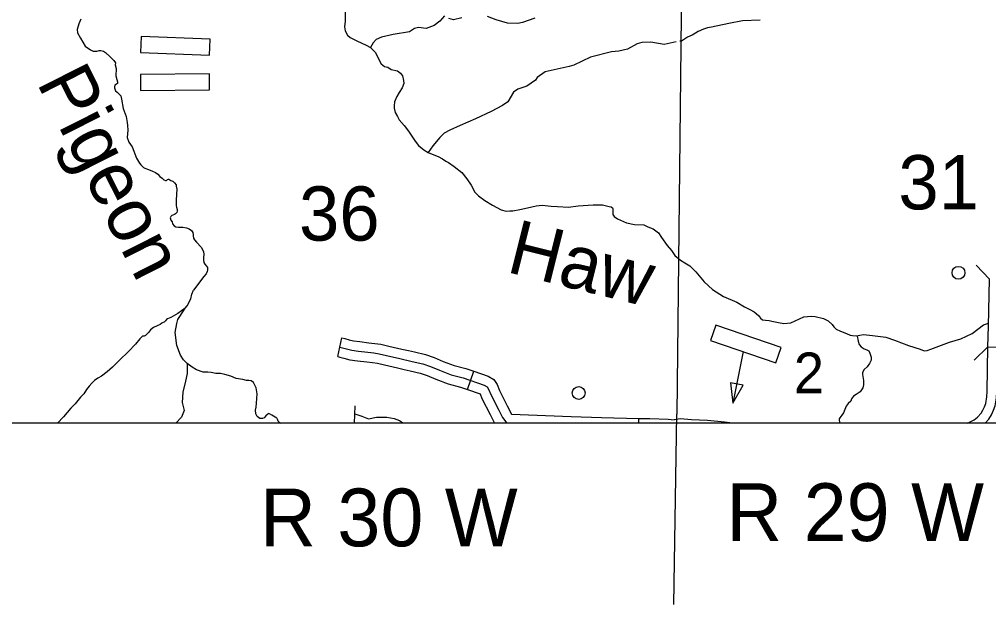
# Model space of a CAD drawing. Extents: x 1382482 to 1385815, y 1168351 to 1170484.
# Drawn here: x 1383865.9 to 1384167.8, y 1168645.8 to 1168828.2 of the extents above; entities that cross this region are included whole.
import ezdxf

# ---------------------------------------------------------------- set-up
doc = ezdxf.new("R2010")
doc.units = 0
for name, color, linetype in [('35', 7, 'Continuous'), ('38', 7, 'Continuous'), ('4', 7, 'Continuous'), ('45', 7, 'Continuous'), ('5', 7, 'Continuous'), ('57', 7, 'Continuous'), ('Default', 7, 'Continuous'), ('R_Dimension', 7, 'Continuous'), ('R_No Plot', 7, 'Continuous')]:
    doc.layers.add(name, color=color, linetype=linetype)

msp = doc.modelspace()

# ---------------------------------------------------------------- linework, layer by layer
at = {"layer": '35'}
for points in [[(1383967.32, 1168830.76), (1383967.32, 1168827.61), (1383967.16, 1168825.81), (1383967.32, 1168824.54), (1383968.06, 1168823.23), (1383968.87, 1168822.46), (1383971.04, 1168821.48), (1383973.9, 1168820.13), (1383975.23, 1168819.36), (1383976.85, 1168817.84), (1383977.87, 1168815.63), (1383978.61, 1168814.32), (1383979.63, 1168813.51), (1383980.65, 1168813.3), (1383981.74, 1168812.59), (1383983.62, 1168812.09), (1383984.6, 1168811.36), (1383985.26, 1168810.58), (1383985.58, 1168809.15), (1383985.62, 1168808.13), (1383985.13, 1168806.82), (1383984.23, 1168805.39), (1383983.42, 1168804.08), (1383982.76, 1168802.48), (1383982.6, 1168801.17), (1383982.6, 1168800.48), (1383982.92, 1168799.17), (1383983.66, 1168797.86), (1383984.19, 1168796.84), (1383985.71, 1168795.08), (1383987.06, 1168793.36), (1383989.22, 1168790.26), (1383990.2, 1168788.91), (1383991.88, 1168787.48), (1383993.23, 1168786.71), (1383994.42, 1168786.13), (1383996.34, 1168785.4), (1383997.69, 1168784.7), (1383998.75, 1168784.01), (1383999.53, 1168783.56), (1384001.29, 1168782.29), (1384003.74, 1168780.45), (1384005.25, 1168778.52), (1384006.64, 1168776.48), (1384007.75, 1168774.31), (1384008.85, 1168773.17), (1384010.9, 1168771.77), (1384013.23, 1168770.26), (1384016.01, 1168768.79), (1384017.49, 1168768.4)], [(1383998.29, 1168829.21), (1383996.89, 1168827.55), (1383995.1, 1168826.21), (1383992.59, 1168825.27), (1383990.2, 1168825.64), (1383989.01, 1168825.35), (1383987.36, 1168824.31), (1383982.29, 1168823.43), (1383978.7, 1168822.6), (1383977.07, 1168821.86), (1383976.04, 1168820.81), (1383975.23, 1168819.36)], [(1384026.45, 1168828.51), (1384022.58, 1168827.16), (1384021.15, 1168826.86), (1384017.91, 1168827), (1384014.38, 1168828.05), (1384011.74, 1168829.07)], [(1383885, 1168828.24), (1383884.39, 1168826.72), (1383883.86, 1168825.04), (1383883.98, 1168823.94), (1383884.92, 1168822.26), (1383886.31, 1168819.81), (1383888.03, 1168818.66), (1383888.89, 1168818.25), (1383889.3, 1168818.21), (1383889.7, 1168818.25), (1383889.95, 1168818.29), (1383890.4, 1168818.33), (1383890.69, 1168818.41), (1383891.26, 1168818.41), (1383892.03, 1168818.25), (1383892.69, 1168817.8), (1383894.12, 1168816.49), (1383895.27, 1168815.39), (1383895.8, 1168814.65), (1383895.67, 1168814.04), (1383896.04, 1168812.81), (1383895.92, 1168810.52), (1383896.21, 1168809.42), (1383896.41, 1168808.68), (1383896.41, 1168808.23), (1383896.12, 1168808.02), (1383895.63, 1168807.66), (1383895.47, 1168807.17), (1383895.51, 1168806.8), (1383895.84, 1168805.9), (1383896.33, 1168805.49), (1383896.66, 1168805.2), (1383897.11, 1168804.63), (1383897.43, 1168804.3), (1383897.68, 1168803.29), (1383898.17, 1168800.35), (1383899.15, 1168797.89), (1383899.48, 1168796.01), (1383899.59, 1168795.11), (1383899.63, 1168793.6), (1383899.4, 1168791.35), (1383899.97, 1168789.88), (1383900.95, 1168788.49), (1383902.35, 1168784.9)], [(1384003.74, 1168828.66), (1384001.1, 1168827.97), (1383999.68, 1168828.46)], [(1384096.7, 1168827.92), (1384091.16, 1168827.67), (1384086.87, 1168826.86), (1384081.53, 1168825.71), (1384080.22, 1168825.52), (1384078.97, 1168825.15), (1384077.38, 1168824.34), (1384076.52, 1168823.85), (1384075.49, 1168823.26), (1384073.99, 1168822.64), (1384072.1, 1168821.42), (1384071.66, 1168821.34)], [(1384070.52, 1168821.12), (1384069.54, 1168820.93), (1384066.71, 1168820.31), (1384062.55, 1168821.03), (1384059.83, 1168820.93), (1384058.28, 1168820.52), (1384055.3, 1168818.89), (1384052.66, 1168818.23), (1384050.35, 1168818.05), (1384043.84, 1168816.38), (1384038.65, 1168813.91), (1384037.19, 1168813.45), (1384029.69, 1168811.84), (1384027.2, 1168810.02), (1384026.62, 1168809.2), (1384023.92, 1168807.38), (1384021.15, 1168806.43), (1384019.8, 1168805.46), (1384018.03, 1168802.42), (1384016.38, 1168801.33), (1384012.87, 1168799.5), (1384007.93, 1168797.14), (1384003.15, 1168795.06), (1383999.99, 1168793.67), (1383998.25, 1168792.7), (1383996.9, 1168791.38), (1383994.66, 1168788.81), (1383993.27, 1168786.65)], [(1383902.35, 1168784.9), (1383903.33, 1168783.4), (1383903.67, 1168782.87), (1383904.08, 1168782.42), (1383904.51, 1168782.03), (1383904.96, 1168781.79), (1383906.05, 1168781.38), (1383907.38, 1168780.85), (1383908.23, 1168780.48), (1383908.97, 1168779.93), (1383909.62, 1168779.25), (1383910.32, 1168778.66), (1383910.87, 1168778.17), (1383911.42, 1168777.92), (1383911.71, 1168777.96), (1383911.85, 1168778.05), (1383911.96, 1168778.25), (1383912.3, 1168778.35), (1383912.47, 1168778.33), (1383913, 1168778.01), (1383913.67, 1168777.7), (1383914.23, 1168777.19), (1383914.7, 1168776.61), (1383914.76, 1168776.23), (1383914.9, 1168775.24), (1383914.78, 1168773.69), (1383914.76, 1168771.75), (1383914.68, 1168770.48), (1383914.76, 1168770.03), (1383914.84, 1168769.6), (1383915, 1168768.92), (1383915.06, 1168768.37), (1383914.92, 1168767.98), (1383914.53, 1168767.57), (1383914.16, 1168767.35), (1383913.67, 1168767.16), (1383913.33, 1168767.04), (1383913.06, 1168766.73), (1383912.88, 1168766.32), (1383913.02, 1168765.64), (1383913.43, 1168765.03), (1383913.55, 1168764.45), (1383914.08, 1168763.82), (1383914.61, 1168763.49), (1383915.45, 1168763.47), (1383916.07, 1168763.47), (1383916.8, 1168763.45), (1383917.93, 1168763.21), (1383918.78, 1168762.92), (1383919.44, 1168762.35), (1383919.95, 1168761.71), (1383920.01, 1168761.06), (1383920.01, 1168760.73), (1383920.13, 1168760.02), (1383920.42, 1168759.46), (1383921.05, 1168758.75), (1383922.51, 1168757.16), (1383923.26, 1168755.81), (1383923.32, 1168754.91), (1383923.26, 1168753.99), (1383923.24, 1168753.17), (1383923.37, 1168752.39), (1383923.59, 1168751.94), (1383924.14, 1168751.29), (1383924.45, 1168750.86), (1383924.49, 1168750.08), (1383924.39, 1168749.57), (1383924.1, 1168748.84), (1383923.3, 1168748.04), (1383920.1, 1168743.84)], [(1384017.49, 1168768.4), (1384018.64, 1168768.46), (1384019.61, 1168768.52), (1384021.78, 1168768.89), (1384024.2, 1168769.43), (1384026.91, 1168770.04), (1384028.72, 1168770.28), (1384031.56, 1168769.97), (1384033.56, 1168769.91), (1384036.94, 1168769.61), (1384039.96, 1168770.04), (1384041.47, 1168770.22), (1384044.67, 1168770.4), (1384047.51, 1168770.34), (1384049.56, 1168769.91), (1384050.23, 1168769.73), (1384050.65, 1168769.43), (1384050.77, 1168769.25), (1384050.71, 1168768.89), (1384050.71, 1168768.22), (1384050.77, 1168767.38), (1384051.19, 1168766.71), (1384052.22, 1168766.05), (1384055.06, 1168764.72), (1384057.53, 1168764.24), (1384060.43, 1168764.17), (1384061.64, 1168763.57), (1384063.33, 1168762.91), (1384065.02, 1168761.7), (1384065.87, 1168760.19), (1384067.7, 1168757.71), (1384069.03, 1168756.14), (1384070.1, 1168754.63), (1384071.79, 1168753.18), (1384073.18, 1168752.33), (1384074.78, 1168751.34), (1384076.66, 1168749.52), (1384079.19, 1168746.44), (1384081.79, 1168744.03), (1384085.23, 1168741.79), (1384089.4, 1168740.1), (1384091.81, 1168738.59), (1384093.45, 1168737.8), (1384094.77, 1168737.08), (1384096.16, 1168735.93), (1384096.71, 1168735.02), (1384097.43, 1168734.54), (1384098.34, 1168734.42), (1384099.42, 1168734.36), (1384100.33, 1168734.12), (1384102.38, 1168733.76), (1384103.98, 1168733.39), (1384106.21, 1168733.63), (1384107.6, 1168734.24), (1384110.26, 1168735.45), (1384112.55, 1168735.69), (1384113.77, 1168735.59), (1384116.42, 1168734.98), (1384117.81, 1168734.24), (1384119.08, 1168733.09), (1384119.56, 1168732.37), (1384120.29, 1168731.64), (1384121.67, 1168731.04), (1384123.55, 1168730.25), (1384124.69, 1168729.77), (1384125.43, 1168729.67), (1384126.57, 1168729.53), (1384128.86, 1168729.95), (1384131.7, 1168729.71), (1384134.12, 1168729.35), (1384135.81, 1168729.1)], [(1383919.72, 1168719.85), (1383918.14, 1168720.95), (1383916.96, 1168722.05), (1383916.02, 1168723.59), (1383914.95, 1168726.58), (1383914.42, 1168730.59), (1383914.87, 1168733.41), (1383915.24, 1168734.68), (1383915.9, 1168735.58), (1383917.55, 1168738.22), (1383918.14, 1168738.93), (1383919.29, 1168741.14), (1383919.58, 1168742.53), (1383920.1, 1168743.84)], [(1383917.55, 1168738.22), (1383915.22, 1168736.55), (1383913.06, 1168735.31), (1383911.99, 1168734.84), (1383911.74, 1168734.66), (1383911.42, 1168734.22), (1383910.95, 1168733.82), (1383910.7, 1168733.73), (1383910.21, 1168733.53), (1383909.7, 1168733.08), (1383908.82, 1168732.71), (1383907.68, 1168732.12), (1383906.73, 1168731.45), (1383906.04, 1168730.63), (1383905.12, 1168729.62), (1383904.69, 1168729.42), (1383904.26, 1168729.42), (1383903.93, 1168729.11), (1383903.44, 1168728.66), (1383901.99, 1168726.99), (1383899.82, 1168724.7), (1383897.06, 1168721.97), (1383894.86, 1168719.81), (1383893.22, 1168718.35), (1383891.44, 1168717), (1383890.34, 1168716.35), (1383889.29, 1168715.68), (1383888.41, 1168714.86), (1383887.62, 1168713.85), (1383886.78, 1168712.85), (1383885.92, 1168711.54), (1383884.92, 1168710.48), (1383883.2, 1168708.43), (1383881.93, 1168706.98), (1383879.56, 1168704.36), (1383877.74, 1168702.36)], [(1384135.81, 1168729.1), (1384138.49, 1168728.22), (1384142.84, 1168726.58), (1384146.53, 1168725.38), (1384147.74, 1168724.89), (1384148.64, 1168724.95), (1384149.79, 1168725.44), (1384152.27, 1168726.34), (1384155.59, 1168727.55), (1384159.21, 1168728.64), (1384162.71, 1168730.33), (1384166.22, 1168732.99), (1384167.78, 1168733.53)], [(1384126.9, 1168729.59), (1384127.2, 1168727.93), (1384127.54, 1168726.83), (1384128.09, 1168726.15), (1384129.02, 1168725.52), (1384129.87, 1168725.22), (1384130.5, 1168724.89), (1384130.84, 1168724.13), (1384131.22, 1168722.9), (1384131.22, 1168721.97), (1384130.67, 1168720.91), (1384130.03, 1168719.9), (1384129.02, 1168719.1), (1384128.51, 1168718.17), (1384128.56, 1168717.49), (1384128.89, 1168715.63), (1384128.81, 1168714.28), (1384128.68, 1168713.35), (1384127.79, 1168712.12), (1384126.57, 1168711.32), (1384125.77, 1168710.77), (1384125.13, 1168709.89), (1384124.88, 1168709.16), (1384124.09, 1168708.51), (1384123.46, 1168707.62), (1384122.6, 1168705.57), (1384122.13, 1168704.86), (1384121.49, 1168703.98), (1384121.31, 1168703.73), (1384121.38, 1168702.36)], [(1383918.14, 1168720.95), (1383918.14, 1168717.88), (1383917.61, 1168715.46), (1383916.79, 1168712.02), (1383916.63, 1168708.75), (1383917.2, 1168706.31), (1383916.38, 1168704.19), (1383914.63, 1168702.36)], [(1383946.11, 1168703.91), (1383944.5, 1168704.88), (1383943.81, 1168705.29), (1383943.46, 1168705.33), (1383943.27, 1168705.21), (1383942.62, 1168704.59), (1383942.17, 1168704.06), (1383941.6, 1168703.77), (1383940.74, 1168703.81), (1383939.92, 1168704.39), (1383939.57, 1168705.23), (1383939.47, 1168706.43), (1383939.61, 1168707.33), (1383939.76, 1168708.56), (1383939.96, 1168711.46), (1383939.68, 1168713.39), (1383938.82, 1168715.02), (1383938.04, 1168715.51), (1383937.39, 1168715.64), (1383936.61, 1168715.68), (1383935.45, 1168715.95), (1383933.37, 1168716.32), (1383931.72, 1168716.96), (1383929.9, 1168717.48), (1383928.47, 1168717.81), (1383927.08, 1168717.85), (1383925.65, 1168718.09), (1383924.61, 1168718.29), (1383923.13, 1168718.29), (1383921.09, 1168718.93), (1383919.72, 1168719.85), (1383919.71, 1168719.85)], [(1383970.38, 1168707.79), (1383970.18, 1168702.36)], [(1383970.29, 1168705.29), (1383970.38, 1168705.27), (1383972.52, 1168704.51), (1383974.62, 1168703.74), (1383977.14, 1168704.18), (1383979.02, 1168704.24), (1383980.34, 1168704.24), (1383982.65, 1168703.79), (1383984.29, 1168703.21), (1383985.19, 1168702.53), (1383985.28, 1168702.36)], [(1383946.11, 1168703.91), (1383946.2, 1168703.75), (1383946.38, 1168703.12), (1383946.85, 1168702.68), (1383947.19, 1168702.36)]]:
    msp.add_lwpolyline(points, dxfattribs=at)
at = {"layer": '38'}
for points in [[(1384168.07, 1168747.22), (1384163.92, 1168751.55)], [(1384163.3, 1168721.94), (1384167.63, 1168726.1)]]:
    msp.add_lwpolyline(points, dxfattribs=at)
at = {"layer": '4'}
msp.add_lwpolyline([(1384072.84, 1168894.38), (1384072.4, 1168859.16), (1384072.39, 1168858.03), (1384070.68, 1168705.11)], dxfattribs=at)
at = {"layer": '45'}
for p, q in [((1383965.04, 1168723.11), (1383966.29, 1168728.98)), ((1384005.48, 1168712.84), (1384007.43, 1168718.51)), ((1384058.8, 1168702.36), (1384058.84, 1168703.85))]:
    msp.add_line(p, q, dxfattribs=at)
for points in [[(1383965.67, 1168726.05), (1383966.51, 1168725.87), (1383967.78, 1168725.47), (1383969.41, 1168725.05), (1383971.55, 1168724.78), (1383974.42, 1168724.45), (1383976.27, 1168724.23), (1383977.96, 1168723.99), (1383980.25, 1168723.45), (1383984.36, 1168722.51), (1383988.25, 1168721.61), (1383991.55, 1168720.82), (1383993.99, 1168720), (1383996.71, 1168718.83), (1384000.39, 1168717.44), (1384004.14, 1168716.47), (1384010.66, 1168714.24), (1384011.57, 1168713.69), (1384012.05, 1168712.97), (1384012.71, 1168711.27), (1384015.19, 1168706.44), (1384016.34, 1168704.15), (1384017.43, 1168702.79), (1384017.72, 1168702.36)], [(1383966.29, 1168728.98), (1383967.27, 1168728.77), (1383968.6, 1168728.36), (1383969.98, 1168728), (1383971.92, 1168727.76), (1383974.77, 1168727.43), (1383976.65, 1168727.21), (1383978.52, 1168726.94), (1383980.93, 1168726.37), (1383985.03, 1168725.44), (1383987.05, 1168724.97)], [(1383965.04, 1168723.11), (1383965.75, 1168722.96), (1383966.96, 1168722.59), (1383968.84, 1168722.1), (1383971.19, 1168721.8), (1383974.08, 1168721.47), (1383975.88, 1168721.26), (1383977.4, 1168721.04), (1383979.57, 1168720.53), (1383983.69, 1168719.59), (1383985.69, 1168719.12)], [(1383987.05, 1168724.97), (1383988.94, 1168724.53), (1383992.37, 1168723.71), (1383995.06, 1168722.81), (1383997.84, 1168721.61), (1384001.3, 1168720.3), (1384005, 1168719.35), (1384007.43, 1168718.51)], [(1383985.69, 1168719.12), (1383987.57, 1168718.69), (1383990.72, 1168717.93), (1383992.92, 1168717.2), (1383995.58, 1168716.05), (1383999.49, 1168714.57), (1384003.28, 1168713.59), (1384005.48, 1168712.84)], [(1384007.43, 1168718.51), (1384011.93, 1168716.97), (1384013.69, 1168715.92), (1384014.73, 1168714.36), (1384015.45, 1168712.51), (1384017.87, 1168707.8), (1384019.21, 1168705.12)], [(1384005.48, 1168712.84), (1384009.39, 1168711.5), (1384009.41, 1168711.49), (1384009.98, 1168710.04), (1384012.51, 1168705.09), (1384013.87, 1168702.36)], [(1384019.21, 1168705.12), (1384037.75, 1168704.48)], [(1384037.75, 1168704.48), (1384047.27, 1168704.15), (1384058.84, 1168703.85)], [(1384058.84, 1168703.85), (1384062.27, 1168703.76), (1384068, 1168703.65), (1384069.88, 1168703.37)], [(1384087.21, 1168702.44), (1384085.58, 1168702.66), (1384080.2, 1168703.15), (1384075.23, 1168703.39), (1384071.7, 1168703.68), (1384069.88, 1168703.37)], [(1384087.8, 1168702.36), (1384087.21, 1168702.44)]]:
    msp.add_lwpolyline(points, dxfattribs=at)
at = {"layer": '57'}
for p, q in [((1383903.8, 1168822.83), (1383903.61, 1168817.83)), ((1383925.28, 1168822.01), (1383903.8, 1168822.83)), ((1383925.09, 1168817.01), (1383925.28, 1168822.01)), ((1383903.61, 1168817.83), (1383925.09, 1168817.01)), ((1383925.09, 1168811.17), (1383903.59, 1168810.99)), ((1383903.59, 1168810.99), (1383903.63, 1168805.99)), ((1383925.13, 1168806.17), (1383925.09, 1168811.17)), ((1383903.63, 1168805.99), (1383925.13, 1168806.17)), ((1384082.81, 1168732.88), (1384081.19, 1168728.15)), ((1384103.15, 1168725.92), (1384082.81, 1168732.88)), ((1384081.19, 1168728.15), (1384101.53, 1168721.19)), ((1384101.53, 1168721.19), (1384103.15, 1168725.92))]:
    msp.add_line(p, q, dxfattribs=at)
msp.add_lwpolyline([(1384091.36, 1168724.67), (1384088.18, 1168708.56)], dxfattribs=at)
msp.add_lwpolyline([(1384091.36, 1168714.17), (1384087.36, 1168714.96), (1384088.18, 1168708.56)], close=True, dxfattribs=at)
at = {"layer": 'Default'}
msp.add_line((1384167.63, 1168726.1), (1384173.63, 1168725.97), dxfattribs=at)
for points in [[(1384166.76, 1168702.36), (1384167.86, 1168703.6), (1384168.73, 1168704.94), (1384169.35, 1168706.36), (1384169.87, 1168707.74), (1384170.24, 1168710.26), (1384170.35, 1168712.16), (1384170.76, 1168732.56), (1384172.28, 1168804.42), (1384172.97, 1168852.13), (1384172.97, 1168888.73), (1384172.69, 1168911.31), (1384172.24, 1168922.6)], [(1384167.63, 1168726.1), (1384167.76, 1168732.62), (1384168.07, 1168747.21)], [(1384166.07, 1168706.36), (1384166.57, 1168707.49), (1384166.95, 1168708.5), (1384167.26, 1168710.56), (1384167.35, 1168712.27), (1384167.63, 1168726.1)], [(1384161.28, 1168702.36), (1384162.07, 1168702.73), (1384163.37, 1168703.43), (1384164.37, 1168704.19), (1384165.47, 1168705.42), (1384166.07, 1168706.36), (1384166.07, 1168706.36)]]:
    msp.add_lwpolyline(points, dxfattribs=at)
for centre in [(1384158.43, 1168749.21), (1384040.11, 1168711.77)]:
    msp.add_circle(centre, 2, dxfattribs=at)
at = {"layer": 'R_Dimension'}
msp.add_line((1384069.77, 1168645.82), (1384070.68, 1168705.11), dxfattribs=at)
at = {"layer": 'R_No Plot'}
msp.add_lwpolyline([(1383432.46, 1169579.7), (1384939.88, 1169579.7), (1384939.88, 1168702.36), (1383432.46, 1168702.36)], close=True, dxfattribs=at)

# ---------------------------------------------------------------- texts
at = {"layer": '35'}
for s, rotation, p in [('Pigeon', 296.8457, (1383871.09, 1168808.49)), ('Haw', 345.9606, (1384017.2, 1168749.57))]:
    msp.add_text(s, height=16.896, rotation=rotation, dxfattribs=at).set_placement(p)
at = {"layer": '5'}
for s, p in [('31', (1384139.7, 1168768.96)), ('36', (1383952.97, 1168759.23))]:
    msp.add_text(s, height=16.896, dxfattribs=at).set_placement(p)
at = {"layer": '57'}
msp.add_text('2', height=12.67, dxfattribs=at).set_placement((1384107.12, 1168711.68))
at = {"layer": 'Default'}
for s, p in [('R 29 W', (1384086.14, 1168665.62)), ('R 30 W', (1383940.87, 1168663.98))]:
    msp.add_text(s, height=18, dxfattribs=at).set_placement(p)

doc.saveas('drawing.dxf')
